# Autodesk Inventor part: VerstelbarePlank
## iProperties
Created: 2010-03
Part Number: VerstelbarePlank
Document SubType Name: Modeling
Designer: Ferry
Density: 1 g/cm^3
Author: Ferry
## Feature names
1. Extrusion1
